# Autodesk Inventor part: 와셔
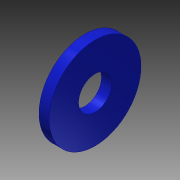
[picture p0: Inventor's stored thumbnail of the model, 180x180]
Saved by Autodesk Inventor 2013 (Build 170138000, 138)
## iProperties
Created: 2015-12
Part Number: 와셔
Material: 스테인리스강
Document SubType Name: Modeling
Designer: mduedu
Density: 8.08 g/cm^3
Mass: 3.57598 g
Surface Area: 5.9651 cm^2
Volume: 0.442572 cm^3
Author: mduedu
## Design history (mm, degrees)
sketch "스케치1"
  geometry: C1 r 3.25 at (0, 0); C2 r 9 at (0, 0); 1 further point
  constraints: 2 centre point, 2 coincident
  dimensions: "d0" = 6.5 diameter of C1; "d1" = 18 diameter of C2
extrude "돌출1" new body sketch "스케치1" stored distance "d2" = 2; taper "d3" = 0 deg
node "솔리드1"
